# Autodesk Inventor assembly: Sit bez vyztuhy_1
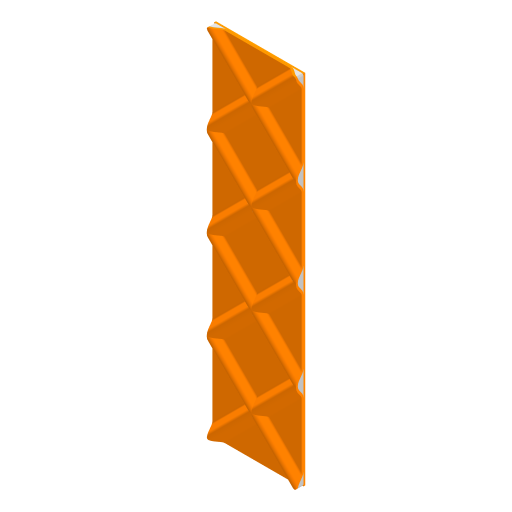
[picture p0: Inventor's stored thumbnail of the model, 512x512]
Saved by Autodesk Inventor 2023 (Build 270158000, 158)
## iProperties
Created: 2025-03
Part Number: Sit bez vyztuhy_1
Document SubType Name: Assembly
Designer: tomik
Author: tomik
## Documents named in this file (4)
- C:\Users\tomik\Desktop\Růčka_Tomáš_přílohy\Vyztužení\Síť žeber\Sit zeber.iam
- C:\Users\tomik\Desktop\Růčka_Tomáš_přílohy\Vyztužení\Síť žeber\Spodni tkanina 50x200.ipt
- C:\Users\tomik\Desktop\Růčka_Tomáš_přílohy\Vyztužení\Síť žeber\Sit zeber vyztuha.ipt
- C:\Users\tomik\Desktop\Růčka_Tomáš_přílohy\Vyztužení\Síť žeber\Horni_tkanina.ipt
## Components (3 placed, 3 different names)
1. Spodni tkanina 50x200:1 — Proti sobě:1, Proti sobě:2, Stejný směr:1, Proti sobě:3, Proti sobě:4, Proti sobě:5
2. Sit zeber vyztuha:1 — Proti sobě:3, Proti sobě:4, Proti sobě:5, Proti sobě:6, Proti sobě:7
3. Horni_tkanina:1 — Proti sobě:6, Proti sobě:7
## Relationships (8: Mate 7, Flush 1)
- Proti sobě:1 [Mate]: Spodni tkanina 50x200:1
- Proti sobě:2 [Mate]: Spodni tkanina 50x200:1
- Stejný směr:1 [Flush]: Spodni tkanina 50x200:1
- Proti sobě:3 [Mate]: Spodni tkanina 50x200:1 ↔ Sit zeber vyztuha:1
- Proti sobě:4 [Mate]: Spodni tkanina 50x200:1 ↔ Sit zeber vyztuha:1
- Proti sobě:5 [Mate]: Spodni tkanina 50x200:1 ↔ Sit zeber vyztuha:1
- Proti sobě:6 [Mate]: Sit zeber vyztuha:1 ↔ Horni_tkanina:1
- Proti sobě:7 [Mate]: Sit zeber vyztuha:1 ↔ Horni_tkanina:1
